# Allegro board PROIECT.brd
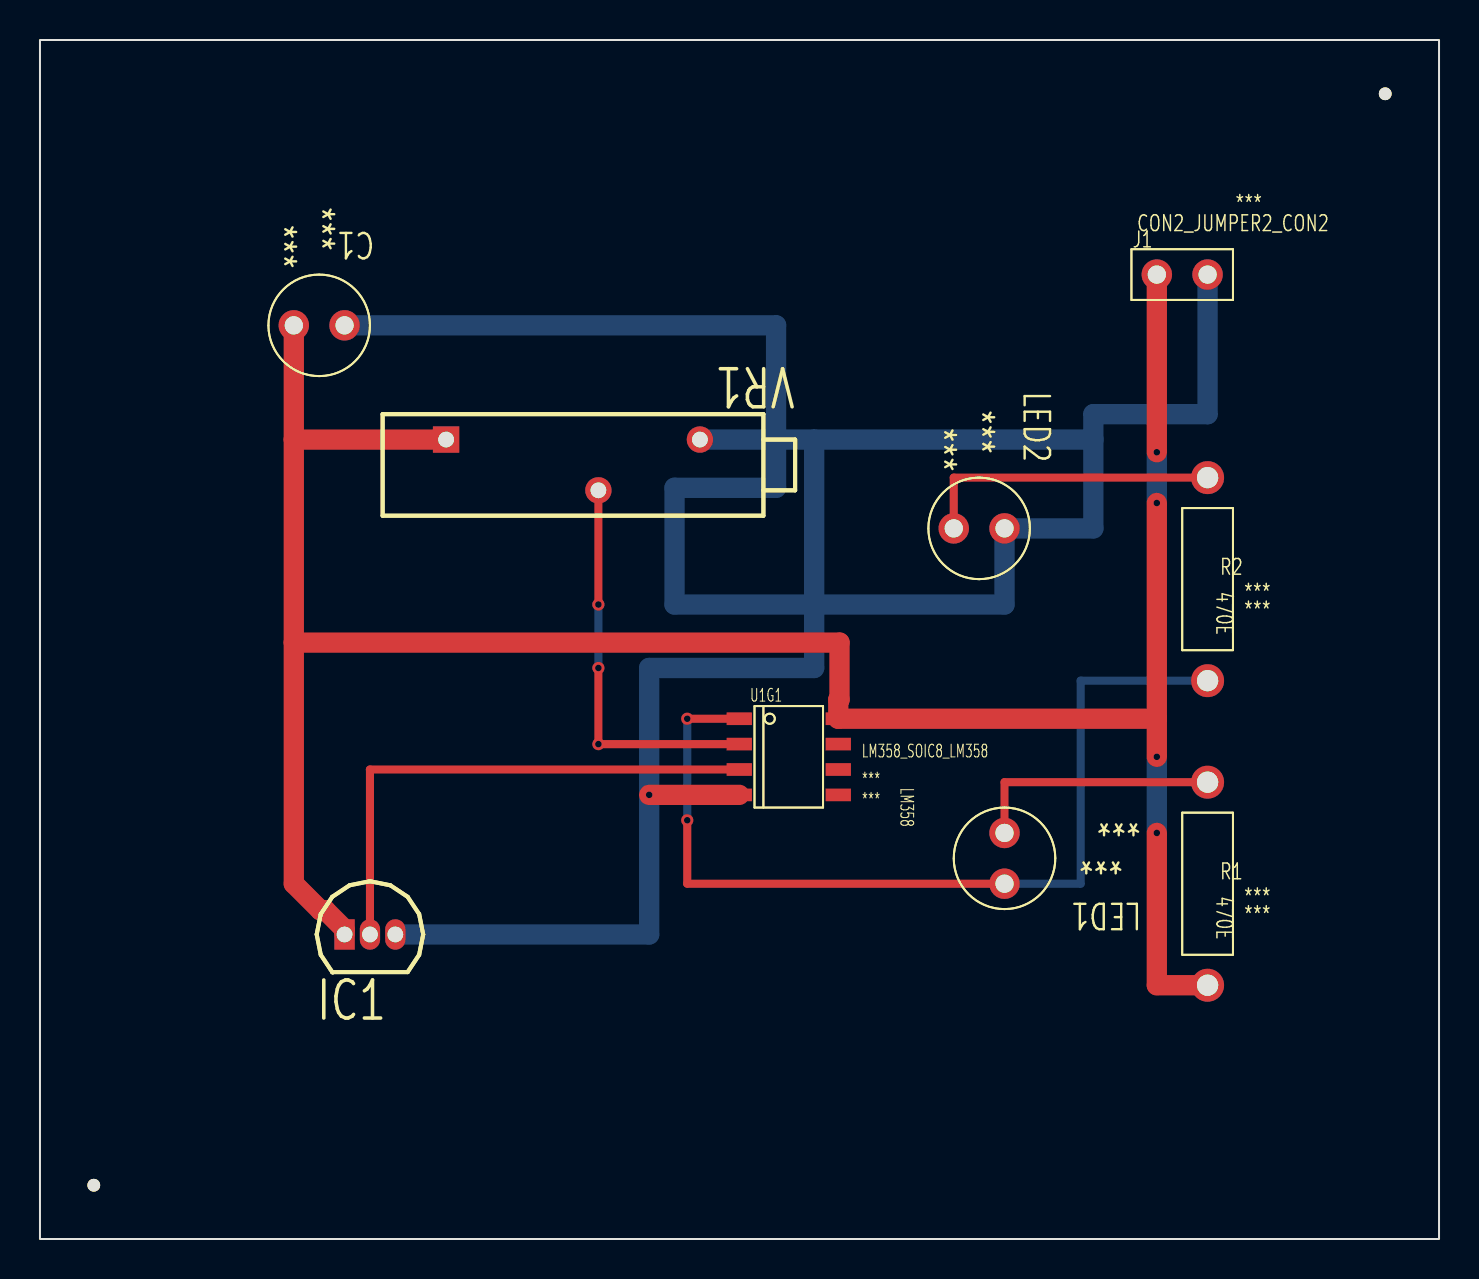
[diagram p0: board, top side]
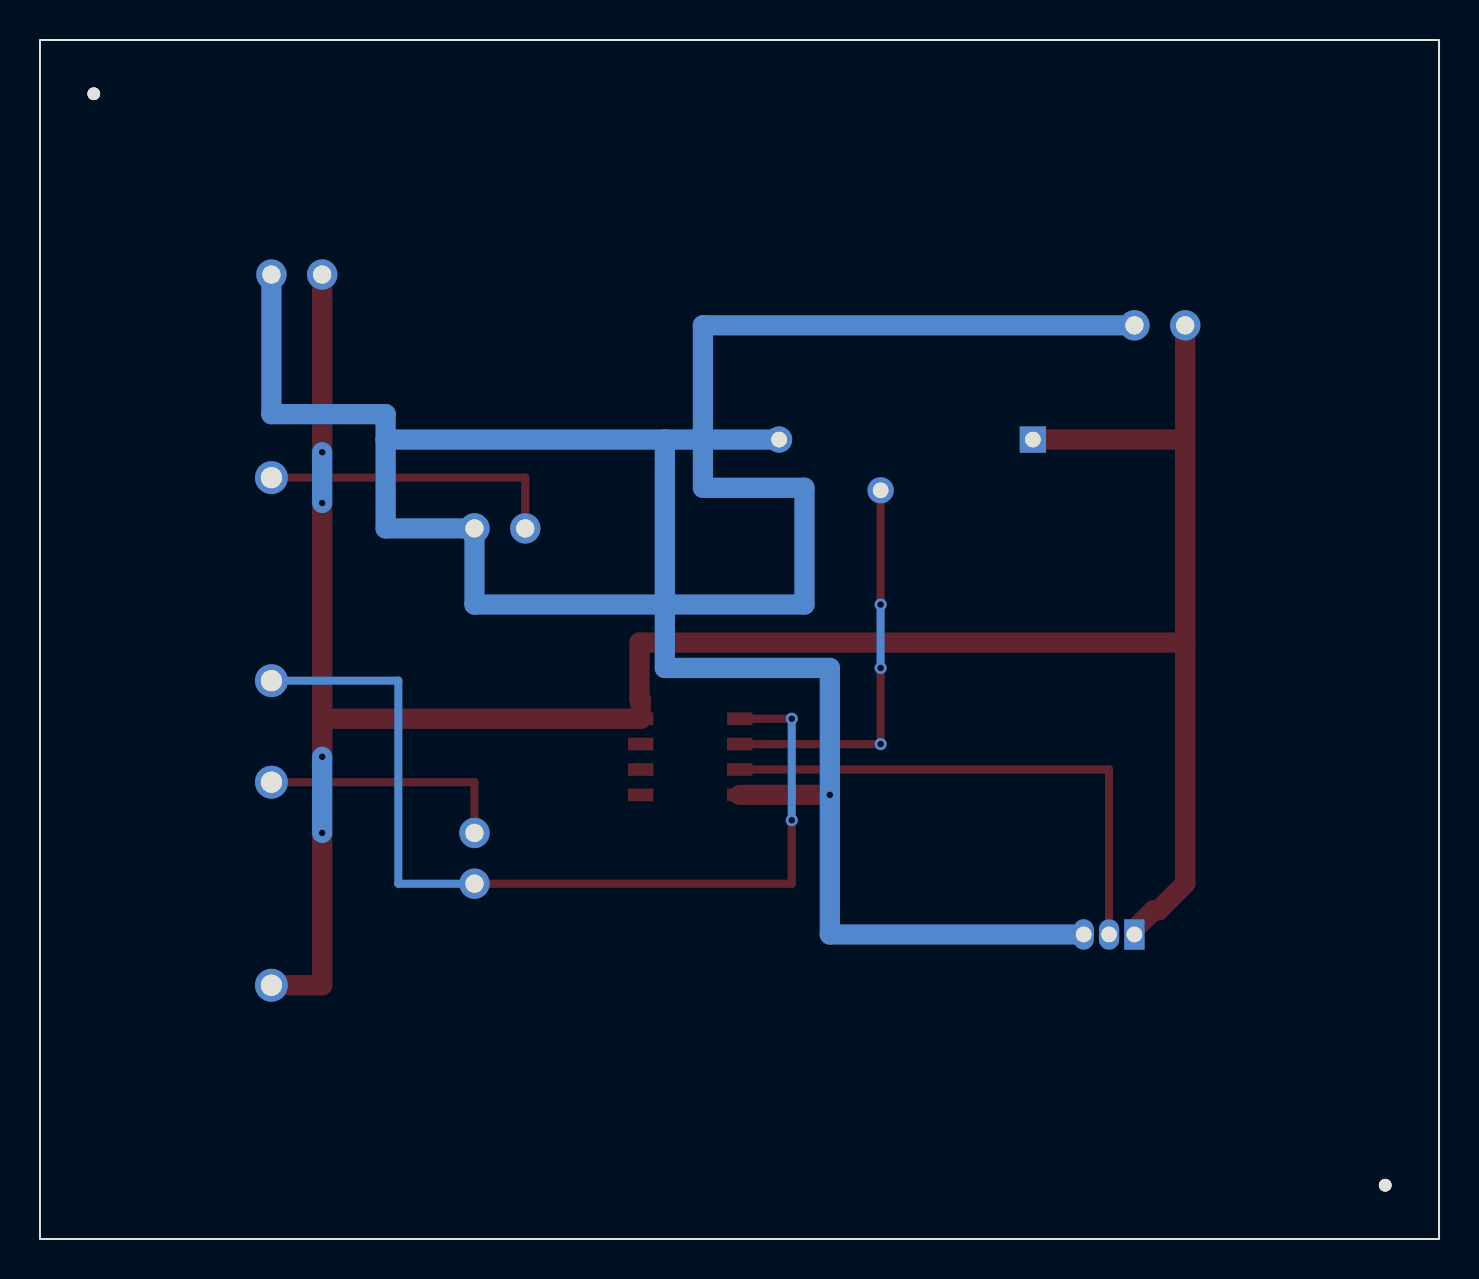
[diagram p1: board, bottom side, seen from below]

Outline 70 x 60 mm; copper layers: TOP, BOTTOM. Coordinates in mm from the lower left corner of the outline.
Outline path: rectangle 0,0 70,60

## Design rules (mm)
nets with their own width: min track width 0.406; nets N00529 N00677 N00684 N00778 N03337
nets with their own width: min track width 1.016; nets +5V GND

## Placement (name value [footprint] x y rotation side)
C1  100uF  [CAP196]  12.7 45.72 270 top
IC1  LM35  [TO92]  15.24 15.24 0 top
J1  CON2  [JUMPER2]  55.88 48.26 0 top
LED1  RED LED  [CAP196]  48.26 20.32 180 top
LED2  GREEN LED  [CAP196]  45.72 35.56 270 top
NOREF  -  [unnamed]  2.69 2.69 0 top
NOREF#2  -  [unnamed]  67.31 57.31 0 top
R1  470E  [RES400]  58.42 12.7 0 top
R2  470E  [RES400]  58.42 27.94 0 top
U1G1  LM358  [SOIC8]  37.47 24.13 0 top
VR1  10k  [VRES9]  20.32 40.01 180 top

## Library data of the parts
C1 = CAP POL: Tolerance: ***; User Part Number: ***
IC1 = LM35/SO_10
J1 = CON2: User Part Number: ***
LED1 LED2 = LED: Tolerance: ***; User Part Number: ***
R1 R2 = R: Tolerance: ***; User Part Number: ***
U1G1 = LM358: Tolerance: ***; User Part Number: ***
VR1 = POT

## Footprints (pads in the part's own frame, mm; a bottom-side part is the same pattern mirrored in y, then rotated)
CAP196
  round 1.524 hole 0.914: 1(0,0) 2(0,2.54)
JUMPER2
  round 1.524 hole 0.914: 1(0,0) 2(2.54,0)
RES400
  round 1.651 hole 1.067: 1(0,0) 2(0,10.16)
SOIC8
  rect 1.27x0.635 smd: 1(-2.477,1.905) 2(-2.477,0.635) 3(-2.477,-0.635) 4(-2.477,-1.905) 5(2.477,-1.905) 6(2.477,-0.635) 7(2.477,0.635) 8(2.477,1.905)
TO92
  rect 1.016x1.524 hole 0.787: 1(0,0)
  oval 1.016x1.524 hole 0.787: 2(1.27,0) 3(2.54,0)
unnamed
  round 0.635 hole 3.175 unplated: (0,0)
VRES9
  rect 1.321x1.321 hole 0.787: 1(0,0)
  round 1.321 hole 0.787: 2(-7.62,2.54) 3(-12.7,0)

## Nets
+5V: C1.1 IC1.1 J1.1 R1.1 U1G1.8 VR1.1
GND: C1.2 IC1.3 J1.2 LED2.2(CATHODE) U1G1.4 VR1.3
N00529: LED2.1 R2.2
N00677: U1G1.2 VR1.2(WIPER)
N00684: IC1.2(VO) U1G1.3
N00778: LED1.2(CATHODE) R2.1 U1G1.1
N03337: LED1.1 R1.2

Pads without a net: U1G1 5 6 7

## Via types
v1: diameter 0.61, hole 0.33, TOP to BOTTOM, 12 vias

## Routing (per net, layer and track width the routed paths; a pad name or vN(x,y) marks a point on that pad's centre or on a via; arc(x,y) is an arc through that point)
+5V: length 124.5
  TOP w1.016: 55.88,26.04 U1G1.8 39.94,26.99 40.01,26.99 40.01,29.84 12.7,29.84 ; 55.88,26.04 v1(55.88,24.13) ; 55.88,26.04 v1(55.88,36.83) ; 12.7,29.84 12.7,17.78 14.03,16.45 14.28,16.45 15.24,15.49 IC1.1 ; 12.7,29.84 12.7,40.01 ; R1.1 55.88,12.7 v1(55.88,20.32) ; 12.7,40.01 C1.1 ; 12.7,40.01 VR1.1 ; J1.1 v1(55.88,39.37)
  BOTTOM w1.016: v1(55.88,24.13) v1(55.88,20.32) ; v1(55.88,39.37) v1(55.88,36.83)
GND: length 153.7
  TOP w1.016: U1G1.4 v1(30.48,22.23)
  BOTTOM w1.016: 52.7,40.01 52.7,41.27 58.42,41.27 J1.2 ; 52.7,40.01 38.73,40.01 ; 52.7,40.01 52.7,35.56 LED2.2 48.26,31.75 31.75,31.75 31.75,37.59 36.83,37.59 36.83,45.72 C1.2 ; 38.73,40.01 38.73,28.57 30.48,28.57 v1(30.48,22.23) 30.48,15.24 IC1.3 ; 38.73,40.01 v1(33.02,40.01)
N00529: length 15.2
  TOP w0.406: R2.2 45.72,38.1 LED2.1
N00677: length 19.7
  TOP w0.406: U1G1.2 v1(27.94,24.77) v1(27.94,28.57) ; v1(27.94,37.47) v1(27.94,31.75)
  BOTTOM w0.406: v1(27.94,31.75) v1(27.94,28.57)
N00684: length 26.7
  TOP w0.406: IC1.2 16.51,23.5 34.99,23.5
N00778: length 47.1
  TOP w0.406: U1G1.1 v1(32.38,26.04) ; LED1.2 32.38,17.78 v1(32.38,20.95)
  BOTTOM w0.406: LED1.2 52.07,17.78 52.07,27.94 R2.1 ; v1(32.38,26.04) v1(32.38,20.95)
N03337: length 12.7
  TOP w0.406: R1.2 48.26,22.86 LED1.1

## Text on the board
TOLERANCE_TOP: FIGURE | FINISHED_SIZE | 13.0 | 31.0 | 36.0 | 42.0 | DRILL CHART: TOP to BOTTOM | ALL UNITS ARE IN MILS | PLATED | QTY | 12 | 6 | 8 | 4
